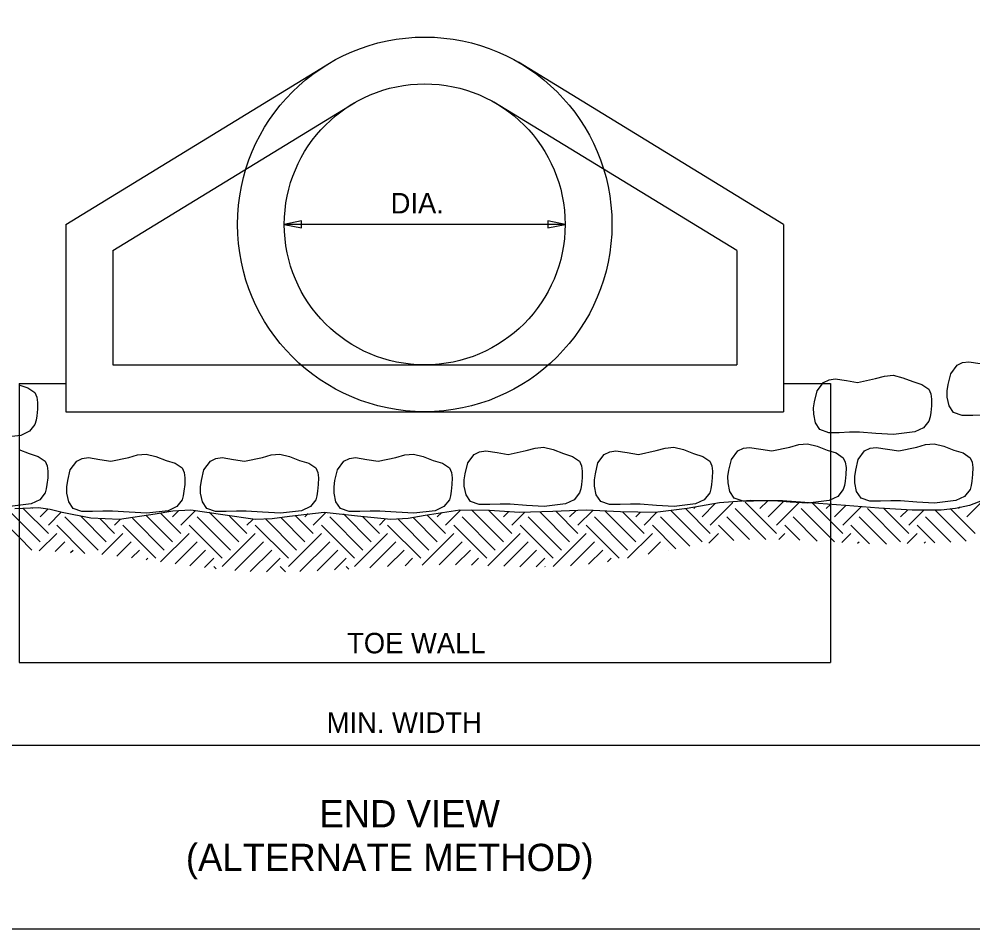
# Model space of a CAD drawing. Extents: x -439.1 to -407.9, y -458.1 to -436.2.
# Drawn here: x -431.65 to -424.66, y -458.05 to -451.39 of the extents above; entities that cross this region are included whole.
import ezdxf

# ---------------------------------------------------------------- set-up
doc = ezdxf.new("R2010")
doc.units = 0
doc.layers.add('Draft_Named_Boundary', color=7, linetype='Continuous')
doc.layers.add('Level 4', color=7, linetype='Continuous')

msp = doc.modelspace()

# ---------------------------------------------------------------- linework, layer by layer
at = {"layer": 'Draft_Named_Boundary'}
msp.add_lwpolyline([(-439.109, -458.0508), (-407.859, -458.0508), (-407.859, -437.6758), (-439.109, -437.6758)], close=True, dxfattribs=at)
at = {"layer": 'Level 4'}
for p, q in [((-431.3083, -452.893), (-429.3653, -451.7055)), ((-426.0507, -452.893), (-427.9937, -451.7055)), ((-430.9654, -453.0851), (-429.187, -451.9981)), ((-426.3936, -453.0851), (-428.1732, -451.9981)), ((-431.3083, -452.893), (-431.3083, -454.2646)), ((-427.6512, -452.8928), (-429.7085, -452.8928)), ((-426.0507, -452.893), (-426.0507, -454.2646)), ((-430.9654, -453.0851), (-430.9654, -453.9217)), ((-426.3936, -453.0851), (-426.3936, -453.9217)), ((-430.9654, -453.9217), (-426.3936, -453.9217)), ((-431.6512, -454.0588), (-431.3083, -454.0588)), ((-431.6512, -454.0588), (-431.6512, -456.1002)), ((-426.0507, -454.0588), (-425.7078, -454.0588)), ((-425.7078, -454.0588), (-425.7078, -456.1002)), ((-431.3083, -454.2646), (-426.0507, -454.2646)), ((-426.1635, -455.0344), (-426.0457, -454.9167)), ((-424.7088, -455.0344), (-424.5854, -454.911)), ((-431.6515, -455.0623), (-431.7316, -454.9822)), ((-431.4369, -455.1557), (-431.6206, -454.972)), ((-431.5582, -454.9738), (-431.5535, -454.9691)), ((-431.4975, -455.0344), (-431.4437, -454.9806)), ((-430.4671, -455.0951), (-430.3602, -454.9882)), ((-428.5275, -455.0951), (-428.4171, -454.9847)), ((-428.1032, -455.2163), (-428.3362, -454.9832)), ((-428.0425, -455.1557), (-428.2099, -454.9883)), ((-427.6182, -455.0344), (-427.5702, -454.9864)), ((-427.5576, -455.0951), (-427.4491, -454.9865)), ((-426.5878, -455.1557), (-426.7696, -454.9739)), ((-426.709, -454.9738), (-426.6963, -454.9611)), ((-426.6484, -455.0344), (-426.551, -454.9371)), ((-426.5878, -455.0951), (-426.4215, -454.9288)), ((-426.1805, -455.1993), (-426.406, -454.9738)), ((-426.1029, -455.1557), (-426.333, -454.9256)), ((-426.2241, -454.9738), (-426.1699, -454.9196)), ((-426.1029, -455.0951), (-425.9329, -454.925)), ((-425.7081, -455.1867), (-425.921, -454.9738)), ((-425.7081, -455.0655), (-425.8419, -454.9318)), ((-425.7392, -454.9738), (-425.7081, -454.9428)), ((-425.7081, -454.9428), (-425.7071, -454.9417)), ((-425.6786, -455.0344), (-425.5942, -454.9501)), ((-425.618, -455.0951), (-425.4811, -454.9582)), ((-425.1937, -455.2163), (-425.4361, -454.9738)), ((-425.1331, -455.1557), (-425.319, -454.9697)), ((-425.1937, -455.0344), (-425.1416, -454.9824)), ((-425.1331, -455.0951), (-425.023, -454.985)), ((-424.7141, -455.2109), (-424.9398, -454.9852)), ((-424.6482, -455.1557), (-424.8299, -454.9739)), ((-424.7694, -454.9738), (-424.7569, -454.9614)), ((-431.6515, -455.1836), (-431.8006, -455.0344)), ((-431.4369, -455.0951), (-431.3427, -455.0008)), ((-431.0732, -455.2769), (-431.3157, -455.0344)), ((-431.0126, -455.2163), (-431.1994, -455.0295)), ((-430.952, -455.1557), (-431.0603, -455.0473)), ((-430.952, -455.0951), (-430.9108, -455.0538)), ((-430.5883, -455.2769), (-430.8212, -455.044)), ((-430.5277, -455.2163), (-430.7178, -455.0262)), ((-430.4671, -455.1557), (-430.6159, -455.0069)), ((-430.5277, -455.0344), (-430.4818, -454.9886)), ((-430.1034, -455.2769), (-430.3459, -455.0344)), ((-430.0428, -455.2163), (-430.2591, -455)), ((-429.9822, -455.1557), (-430.109, -455.0289)), ((-429.9822, -455.0951), (-429.9399, -455.0527)), ((-429.6185, -455.2769), (-429.8445, -455.0509)), ((-429.5579, -455.2163), (-429.7344, -455.0398)), ((-429.4973, -455.1557), (-429.6287, -455.0242)), ((-429.5579, -455.0344), (-429.5341, -455.0106)), ((-429.4973, -455.0951), (-429.4052, -455.003)), ((-429.1336, -455.2769), (-429.376, -455.0344)), ((-429.073, -455.2163), (-429.2762, -455.013)), ((-429.0124, -455.1557), (-429.134, -455.0341)), ((-429.0124, -455.0951), (-428.9691, -455.0518)), ((-428.6487, -455.2769), (-428.875, -455.0505)), ((-428.5881, -455.2163), (-428.7654, -455.0389)), ((-428.5274, -455.1557), (-428.6619, -455.0213)), ((-428.5881, -455.0344), (-428.5551, -455.0015)), ((-428.1638, -455.2769), (-428.4062, -455.0344)), ((-428.1032, -455.0344), (-428.0669, -454.9981)), ((-428.0425, -455.0951), (-427.9493, -455.0018)), ((-427.6789, -455.2769), (-427.9213, -455.0344)), ((-427.6182, -455.2163), (-427.8351, -454.9994)), ((-427.5576, -455.1557), (-427.7201, -454.9932)), ((-427.1939, -455.2769), (-427.4364, -455.0344)), ((-427.1333, -455.2163), (-427.3596, -454.99)), ((-427.0727, -455.1557), (-427.2303, -454.9981)), ((-427.1333, -455.0344), (-427.1023, -455.0034)), ((-427.0727, -455.0951), (-426.9785, -455.0008)), ((-426.7367, -455.2492), (-426.9515, -455.0344)), ((-426.6484, -455.2163), (-426.8742, -454.9905)), ((-426.3, -455.201), (-426.4666, -455.0344)), ((-425.8046, -455.2115), (-425.9817, -455.0344)), ((-425.2968, -455.2344), (-425.4967, -455.0344)), ((-424.8266, -455.2197), (-425.0118, -455.0344)), ((-431.4975, -455.2163), (-431.6515, -455.0623)), ((-431.1691, -455.3023), (-431.3763, -455.0951)), ((-430.6489, -455.3375), (-430.8914, -455.0951)), ((-430.164, -455.3375), (-430.4065, -455.0951)), ((-429.6791, -455.3375), (-429.9216, -455.0951)), ((-429.1942, -455.3375), (-429.4367, -455.0951)), ((-428.7093, -455.3375), (-428.9517, -455.0951)), ((-428.2244, -455.3375), (-428.4668, -455.0951)), ((-427.7395, -455.3375), (-427.9819, -455.0951)), ((-427.2546, -455.3375), (-427.497, -455.0951)), ((-426.8394, -455.2678), (-427.0121, -455.0951)), ((-426.415, -455.2073), (-426.5272, -455.0951)), ((-425.9322, -455.2051), (-426.0423, -455.0951)), ((-425.618, -455.1557), (-425.7081, -455.0655)), ((-425.4216, -455.2308), (-425.5574, -455.0951)), ((-424.9438, -455.2237), (-425.0725, -455.0951)), ((-431.5582, -455.2769), (-431.6515, -455.1836)), ((-431.5042, -455.2836), (-431.3763, -455.1557)), ((-431.0457, -455.31), (-430.8914, -455.1557)), ((-430.6146, -455.3638), (-430.4065, -455.1557)), ((-430.164, -455.3981), (-429.9216, -455.1557)), ((-429.6791, -455.3981), (-429.4367, -455.1557)), ((-429.1942, -455.3981), (-428.9517, -455.1557)), ((-428.699, -455.3878), (-428.4668, -455.1557)), ((-428.2186, -455.3924), (-427.9819, -455.1557)), ((-427.7395, -455.3981), (-427.497, -455.1557)), ((-427.1938, -455.3374), (-427.0121, -455.1557)), ((-426.5986, -455.2271), (-426.5272, -455.1557)), ((-426.0861, -455.1995), (-426.0423, -455.1557)), ((-425.6786, -455.2163), (-425.7081, -455.1867)), ((-425.6233, -455.2216), (-425.5574, -455.1557)), ((-425.1466, -455.2299), (-425.0725, -455.1557)), ((-431.3881, -455.2887), (-431.3157, -455.2163)), ((-430.9368, -455.3223), (-430.8308, -455.2163)), ((-430.5081, -455.3785), (-430.3459, -455.2163)), ((-430.0714, -455.4268), (-429.861, -455.2163)), ((-429.5949, -455.4351), (-429.376, -455.2163)), ((-429.0812, -455.4064), (-428.8911, -455.2163)), ((-428.5752, -455.3852), (-428.4062, -455.2163)), ((-428.1011, -455.396), (-427.9213, -455.2163)), ((-427.6124, -455.3923), (-427.4364, -455.2163)), ((-427.0434, -455.3082), (-426.9515, -455.2163)), ((-425.5083, -455.2278), (-425.4967, -455.2163)), ((-425.0216, -455.2261), (-425.0118, -455.2163)), ((-431.274, -455.2958), (-431.2551, -455.2769)), ((-430.8285, -455.3352), (-430.7702, -455.2769)), ((-430.7214, -455.3494), (-430.7096, -455.3375)), ((-430.4007, -455.3924), (-430.2852, -455.2769)), ((-430.2929, -455.4057), (-430.2246, -455.3375)), ((-429.9578, -455.4343), (-429.8003, -455.2769)), ((-429.8394, -455.4371), (-429.7397, -455.3375)), ((-429.4683, -455.4298), (-429.3154, -455.2769)), ((-429.3403, -455.423), (-429.2548, -455.3375)), ((-428.952, -455.3984), (-428.8305, -455.2769)), ((-428.8243, -455.3919), (-428.7699, -455.3375)), ((-428.4551, -455.3864), (-428.3456, -455.2769)), ((-428.3364, -455.3889), (-428.285, -455.3375)), ((-427.9826, -455.3988), (-427.8607, -455.2769)), ((-427.8631, -455.4005), (-427.8001, -455.3375)), ((-427.4803, -455.3814), (-427.3758, -455.2769)), ((-427.3407, -455.363), (-427.3152, -455.3375)), ((-426.8922, -455.2782), (-426.8909, -455.2769)), ((-430.2082, -455.4146), (-430.2246, -455.3981)), ((-429.7003, -455.4376), (-429.7397, -455.3981)), ((-429.2366, -455.4164), (-429.2548, -455.3981)), ((-427.7988, -455.3994), (-427.8001, -455.3981)), ((-431.6512, -456.1002), (-425.7078, -456.1002)), ((-422.0298, -456.7088), (-435.3292, -456.7088))]:
    msp.add_line(p, q, dxfattribs=at)
for points in [[(-429.582, -452.8666), (-429.7085, -452.8928), (-429.582, -452.9191)], [(-427.7776, -452.9191), (-427.6512, -452.8928), (-427.7776, -452.8666)], [(-425.8238, -454.1911), (-425.8055, -454.1124), (-425.7581, -454.0498), (-425.7177, -454.0302), (-425.6727, -454.0235), (-425.5899, -454.0358), (-425.5084, -454.0498), (-425.3771, -454.0219), (-425.3121, -454.003), (-425.2488, -453.9972), (-425.1782, -454.0152), (-425.1042, -454.0432), (-425.0371, -454.0641), (-424.9859, -454.0991), (-424.9715, -454.1327), (-424.9662, -454.1713), (-424.9672, -454.221), (-424.9728, -454.2699), (-424.9776, -454.3021), (-424.9859, -454.3324), (-425.0259, -454.3823), (-425.0893, -454.4123), (-425.2455, -454.4309), (-425.3755, -454.4237), (-425.4952, -454.4145), (-425.567, -454.4146), (-425.6431, -454.4178), (-425.7202, -454.4178), (-425.7844, -454.3948), (-425.8166, -454.3458), (-425.8304, -454.2831), (-425.8312, -454.2362), (-425.8238, -454.1911)], [(-426.4512, -454.693), (-426.4329, -454.6144), (-426.3855, -454.5517), (-426.3451, -454.5321), (-426.3001, -454.5254), (-426.2173, -454.5377), (-426.1358, -454.5517), (-426.0045, -454.5238), (-425.9395, -454.505), (-425.8762, -454.4991), (-425.8056, -454.5171), (-425.7316, -454.5451), (-425.6645, -454.566), (-425.6133, -454.601), (-425.5989, -454.6346), (-425.5936, -454.6733), (-425.5946, -454.7229), (-425.6002, -454.7718), (-425.605, -454.8041), (-425.6133, -454.8343), (-425.6533, -454.8842), (-425.7167, -454.9142), (-425.8729, -454.9328), (-426.0029, -454.9256), (-426.1226, -454.9164), (-426.1944, -454.9165), (-426.2705, -454.9197), (-426.3476, -454.9197), (-426.4118, -454.8967), (-426.444, -454.8477), (-426.4578, -454.785), (-426.4586, -454.7381), (-426.4512, -454.693)], [(-425.5227, -454.693), (-425.5043, -454.6144), (-425.457, -454.5517), (-425.4166, -454.5321), (-425.3715, -454.5254), (-425.2887, -454.5377), (-425.2072, -454.5517), (-425.0759, -454.5238), (-425.0109, -454.505), (-424.9477, -454.4991), (-424.8771, -454.5171), (-424.8031, -454.5451), (-424.7359, -454.566), (-424.6848, -454.601), (-424.6704, -454.6346), (-424.6651, -454.6733), (-424.6661, -454.7229), (-424.6716, -454.7718), (-424.6764, -454.8041), (-424.6848, -454.8343), (-424.7247, -454.8842), (-424.7882, -454.9142), (-424.9444, -454.9328), (-425.0743, -454.9256), (-425.1941, -454.9164), (-425.2658, -454.9165), (-425.342, -454.9197), (-425.4191, -454.9197), (-425.4832, -454.8967), (-425.5155, -454.8477), (-425.5293, -454.785), (-425.5301, -454.7381), (-425.5227, -454.693)], [(-428.3836, -454.7181), (-428.3653, -454.6395), (-428.3179, -454.5768), (-428.2775, -454.5572), (-428.2325, -454.5505), (-428.1497, -454.5628), (-428.0682, -454.5768), (-427.9369, -454.5489), (-427.8719, -454.5301), (-427.8086, -454.5242), (-427.738, -454.5422), (-427.664, -454.5702), (-427.5969, -454.5911), (-427.5457, -454.6261), (-427.5313, -454.6597), (-427.526, -454.6984), (-427.527, -454.748), (-427.5326, -454.7969), (-427.5374, -454.8292), (-427.5457, -454.8594), (-427.5857, -454.9093), (-427.6491, -454.9393), (-427.8053, -454.9579), (-427.9353, -454.9507), (-428.055, -454.9415), (-428.1267, -454.9416), (-428.2029, -454.9448), (-428.28, -454.9448), (-428.3442, -454.9218), (-428.3764, -454.8728), (-428.3902, -454.8101), (-428.391, -454.7632), (-428.3836, -454.7181)], [(-427.43, -454.7181), (-427.4116, -454.6395), (-427.3643, -454.5768), (-427.3239, -454.5572), (-427.2788, -454.5505), (-427.196, -454.5628), (-427.1145, -454.5768), (-426.9832, -454.5489), (-426.9182, -454.5301), (-426.8549, -454.5242), (-426.7844, -454.5422), (-426.7104, -454.5702), (-426.6432, -454.5911), (-426.5921, -454.6261), (-426.5777, -454.6597), (-426.5724, -454.6984), (-426.5734, -454.748), (-426.5789, -454.7969), (-426.5837, -454.8292), (-426.5921, -454.8594), (-426.632, -454.9093), (-426.6955, -454.9393), (-426.8517, -454.9579), (-426.9816, -454.9507), (-427.1014, -454.9415), (-427.1731, -454.9416), (-427.2493, -454.9448), (-427.3264, -454.9448), (-427.3905, -454.9218), (-427.4228, -454.8728), (-427.4365, -454.8101), (-427.4373, -454.7632), (-427.43, -454.7181)], [(-431.2947, -454.7683), (-431.2764, -454.6897), (-431.229, -454.627), (-431.1886, -454.6074), (-431.1436, -454.6007), (-431.0608, -454.613), (-430.9793, -454.627), (-430.848, -454.5991), (-430.783, -454.5803), (-430.7197, -454.5744), (-430.6491, -454.5924), (-430.5751, -454.6204), (-430.508, -454.6413), (-430.4569, -454.6763), (-430.4425, -454.7099), (-430.4371, -454.7486), (-430.4381, -454.7982), (-430.4437, -454.8471), (-430.4485, -454.8793), (-430.4569, -454.9096), (-430.4968, -454.9595), (-430.5603, -454.9895), (-430.7164, -455.0081), (-430.8464, -455.0009), (-430.9662, -454.9917), (-431.0379, -454.9918), (-431.114, -454.995), (-431.1911, -454.995), (-431.2553, -454.972), (-431.2875, -454.923), (-431.3013, -454.8603), (-431.3021, -454.8134), (-431.2947, -454.7683)], [(-430.316, -454.7683), (-430.2976, -454.6897), (-430.2503, -454.627), (-430.2099, -454.6074), (-430.1649, -454.6007), (-430.0821, -454.613), (-430.0006, -454.627), (-429.8693, -454.5991), (-429.8043, -454.5803), (-429.741, -454.5744), (-429.6704, -454.5924), (-429.5964, -454.6204), (-429.5293, -454.6413), (-429.4781, -454.6763), (-429.4637, -454.7099), (-429.4584, -454.7486), (-429.4594, -454.7982), (-429.465, -454.8471), (-429.4697, -454.8793), (-429.4781, -454.9096), (-429.518, -454.9595), (-429.5815, -454.9895), (-429.7377, -455.0081), (-429.8677, -455.0009), (-429.9874, -454.9917), (-430.0591, -454.9918), (-430.1353, -454.995), (-430.2124, -454.995), (-430.2766, -454.972), (-430.3088, -454.923), (-430.3226, -454.8603), (-430.3234, -454.8134), (-430.316, -454.7683)], [(-429.3373, -454.7683), (-429.3189, -454.6897), (-429.2715, -454.627), (-429.2312, -454.6074), (-429.1861, -454.6007), (-429.1033, -454.613), (-429.0218, -454.627), (-428.8905, -454.5991), (-428.8255, -454.5803), (-428.7622, -454.5744), (-428.6917, -454.5924), (-428.6177, -454.6204), (-428.5505, -454.6413), (-428.4994, -454.6763), (-428.485, -454.7099), (-428.4797, -454.7486), (-428.4807, -454.7982), (-428.4862, -454.8471), (-428.491, -454.8793), (-428.4994, -454.9096), (-428.5393, -454.9595), (-428.6028, -454.9895), (-428.759, -455.0081), (-428.8889, -455.0009), (-429.0087, -454.9917), (-429.0804, -454.9918), (-429.1565, -454.995), (-429.2337, -454.995), (-429.2978, -454.972), (-429.3301, -454.923), (-429.3438, -454.8603), (-429.3446, -454.8134), (-429.3373, -454.7683)]]:
    msp.add_lwpolyline(points, close=True, dxfattribs=at)
for points in [[(-424.5882, -454.2891), (-424.6644, -454.2923), (-424.7415, -454.2923), (-424.8057, -454.2693), (-424.8379, -454.2203), (-424.8517, -454.1576), (-424.8525, -454.1107), (-424.8451, -454.0656), (-424.8451, -454.0656), (-424.8267, -453.987), (-424.7794, -453.9243), (-424.739, -453.9047), (-424.6939, -453.898), (-424.6111, -453.9103)], [(-431.6543, -454.0683), (-431.5871, -454.0892), (-431.536, -454.1242), (-431.5216, -454.1578), (-431.5163, -454.1964), (-431.5173, -454.2461), (-431.5228, -454.295), (-431.5276, -454.3272), (-431.536, -454.3575), (-431.5759, -454.4073), (-431.6394, -454.4374), (-431.7956, -454.456)], [(-431.653, -454.5422), (-431.579, -454.5702), (-431.5119, -454.5911), (-431.4607, -454.6261), (-431.4463, -454.6597), (-431.441, -454.6984), (-431.442, -454.748), (-431.4475, -454.7969), (-431.4523, -454.8292), (-431.4607, -454.8594), (-431.5006, -454.9093), (-431.5641, -454.9393), (-431.7203, -454.9579)], [(-424.5939, -454.9143), (-424.69, -454.9499), (-424.7919, -454.9739), (-424.8964, -454.9853), (-425.1087, -454.9848), (-425.3536, -454.9701), (-425.597, -454.9499), (-426.0597, -454.9156), (-426.2912, -454.9141), (-426.5215, -454.9324), (-426.7569, -454.9719), (-426.9925, -455.0022), (-427.2449, -454.9974), (-427.4983, -454.9848), (-427.7426, -454.9945), (-427.9867, -455.0022), (-428.205, -454.9885), (-428.4228, -454.9848), (-428.676, -455.0239), (-428.8022, -455.0451), (-428.9286, -455.0545), (-429.1725, -455.0284), (-429.417, -455.0022), (-429.6702, -455.0306), (-429.7967, -455.0487), (-429.9229, -455.0545), (-430.1585, -455.0193), (-430.3938, -454.9848), (-430.5244, -454.9923), (-430.6551, -455.0141), (-430.9171, -455.0545), (-431.127, -455.044), (-431.3357, -455.0022), (-431.423, -454.9814), (-431.5102, -454.9673), (-431.6833, -454.9746)]]:
    msp.add_lwpolyline(points, dxfattribs=at)
for radius in [1.3715, 1.0287]:
    msp.add_circle((-428.6798, -452.8928), radius, dxfattribs=at)

# ---------------------------------------------------------------- texts
for s, height, p in [('DIA.', 0.15, (-428.9296, -452.8127)), ('TOE WALL', 0.15, (-429.2486, -456.0334)), ('MIN. WIDTH', 0.15, (-429.3986, -456.6154)), ('END VIEW', 0.2, (-429.4514, -457.3076)), ('(ALTERNATE METHOD)', 0.2, (-430.4298, -457.6276))]:
    msp.add_text(s, height=height, dxfattribs=at).set_placement(p)

doc.saveas('drawing.dxf')
